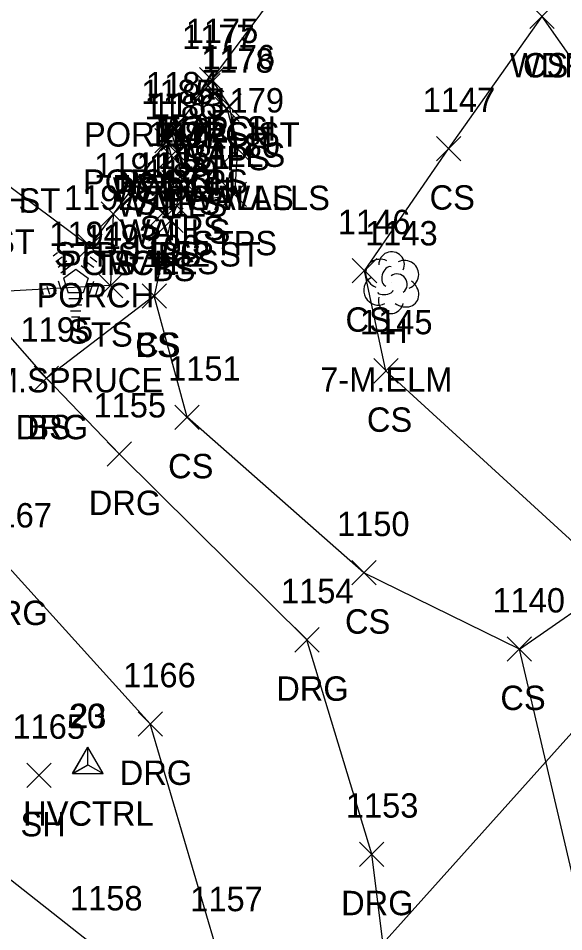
# Model space of a CAD drawing. Extents: x 1537342 to 1542195, y 163002 to 168596.
# Drawn here: x 1541986.2 to 1542030.9, y 163219.8 to 163294.7 of the extents above; entities that cross this region are included whole.
import ezdxf

# ---------------------------------------------------------------- set-up
doc = ezdxf.new("R2010")
doc.units = 0
for name, color, linetype in [('C_A', 7, 'Continuous'), ('C_I', 7, 'Continuous'), ('CPSM', 7, 'Continuous'), ('DCP', 7, 'Continuous'), ('L_A', 7, 'Continuous'), ('L_C', 7, 'Continuous'), ('L_I', 7, 'Continuous'), ('L_TIC', 7, 'Continuous'), ('LAWA', 7, 'Continuous'), ('LBF', 7, 'Continuous'), ('LELB', 7, 'Continuous'), ('LTC', 7, 'Continuous'), ('LTD', 7, 'Continuous'), ('LWS', 7, 'Continuous'), ('R_A', 7, 'Continuous'), ('R_I', 7, 'Continuous'), ('R_TIC', 7, 'Continuous'), ('RDG', 7, 'Continuous')]:
    doc.layers.add(name, color=color, linetype=linetype)

msp = doc.modelspace()

# ---------------------------------------------------------------- linework, layer by layer
at = {"layer": 'CPSM'}
for p, q in [((1541990.659, 163232.721), (1541991.909, 163234.886)), ((1541990.671, 163232.733), (1541991.921, 163234.898)), ((1541993.159, 163232.721), (1541991.909, 163234.886)), ((1541991.909, 163233.442), (1541991.909, 163234.886)), ((1541993.171, 163232.733), (1541991.921, 163234.898)), ((1541991.922, 163233.454), (1541991.921, 163234.898)), ((1541990.659, 163232.721), (1541991.909, 163233.442)), ((1541990.671, 163232.733), (1541991.922, 163233.454)), ((1541991.909, 163233.442), (1541991.909, 163233.442)), ((1541991.909, 163233.442), (1541993.159, 163232.721)), ((1541991.922, 163233.454), (1541991.922, 163233.454)), ((1541991.922, 163233.454), (1541993.171, 163232.733)), ((1541990.659, 163232.721), (1541993.159, 163232.721)), ((1541990.671, 163232.733), (1541993.171, 163232.733))]:
    msp.add_line(p, q, dxfattribs=at)
at = {"layer": 'DCP'}
msp.add_lwpolyline([(1541974.927, 163172.921), (1542058.961, 163266.56)], dxfattribs=at)
at = {"layer": 'L_TIC'}
for points in [[(1542028.159, 163293.803), (1542030.159, 163295.803)], [(1542030.159, 163293.803), (1542028.159, 163295.803)], [(1542028.159, 163293.803), (1542030.159, 163295.803)], [(1542030.159, 163293.803), (1542028.159, 163295.803)], [(1542001.066, 163288.621), (1542003.066, 163290.621)], [(1542003.066, 163288.621), (1542001.066, 163290.621)], [(1542001.066, 163288.621), (1542003.066, 163290.621)], [(1542003.066, 163288.621), (1542001.066, 163290.621)], [(1542000.763, 163288.132), (1542002.763, 163290.132)], [(1542002.763, 163288.132), (1542000.763, 163290.132)], [(1542000.763, 163288.132), (1542002.763, 163290.132)], [(1542002.763, 163288.132), (1542000.763, 163290.132)], [(1542002.326, 163286.194), (1542004.326, 163288.194)], [(1542004.326, 163286.194), (1542002.326, 163288.194)], [(1542002.496, 163286.468), (1542004.496, 163288.468)], [(1542004.496, 163286.468), (1542002.496, 163288.468)], [(1541997.811, 163284.259), (1541999.811, 163286.259)], [(1541999.811, 163284.259), (1541997.811, 163286.259)], [(1541997.811, 163284.259), (1541999.811, 163286.259)], [(1541999.811, 163284.259), (1541997.811, 163286.259)], [(1541997.418, 163283.621), (1541999.418, 163285.621)], [(1541999.418, 163283.621), (1541997.418, 163285.621)], [(1541997.418, 163283.621), (1541999.418, 163285.621)], [(1541999.418, 163283.621), (1541997.418, 163285.621)], [(1541997.75, 163282.381), (1541999.75, 163284.381)], [(1541999.75, 163282.381), (1541997.75, 163284.381)], [(1541998.276, 163282.559), (1542000.276, 163284.559)], [(1542000.276, 163282.559), (1541998.276, 163284.559)], [(1542003.185, 163282.928), (1542005.185, 163284.928)], [(1542005.185, 163282.928), (1542003.185, 163284.928)], [(1542003.185, 163282.928), (1542005.185, 163284.928)], [(1542005.185, 163282.928), (1542003.185, 163284.928)], [(1542020.498, 163282.961), (1542022.498, 163284.961)], [(1542022.498, 163282.961), (1542020.498, 163284.961)], [(1541997.993, 163280.174), (1541999.993, 163282.174)], [(1541999.993, 163280.174), (1541997.993, 163282.174)], [(1541998.645, 163280.46), (1542000.645, 163282.46)], [(1542000.645, 163280.46), (1541998.645, 163282.46)], [(1542002.929, 163279.223), (1542004.929, 163281.223)], [(1542004.929, 163279.223), (1542002.929, 163281.223)], [(1541998.201, 163278.299), (1542000.201, 163280.299)], [(1542000.201, 163278.299), (1541998.201, 163280.299)], [(1541998.201, 163278.299), (1542000.201, 163280.299)], [(1542000.201, 163278.299), (1541998.201, 163280.299)], [(1541993.003, 163277.598), (1541995.003, 163279.598)], [(1541995.003, 163277.598), (1541993.003, 163279.598)], [(1541993.003, 163277.598), (1541995.003, 163279.598)], [(1541995.003, 163277.598), (1541993.003, 163279.598)], [(1541997.044, 163277.667), (1541999.044, 163279.667)], [(1541999.044, 163277.667), (1541997.044, 163279.667)], [(1541997.733, 163277.097), (1541999.733, 163279.097)], [(1541999.733, 163277.097), (1541997.733, 163279.097)], [(1541991.084, 163274.946), (1541993.084, 163276.946)], [(1541993.084, 163274.946), (1541991.084, 163276.946)], [(1542013.6, 163272.951), (1542015.6, 163274.951)], [(1542015.6, 163272.951), (1542013.6, 163274.951)], [(1541992.771, 163271.734), (1541994.771, 163273.734)], [(1541994.771, 163271.734), (1541992.771, 163273.734)], [(1541996.358, 163270.883), (1541998.358, 163272.883)], [(1541998.358, 163270.883), (1541996.358, 163272.883)], [(1541996.358, 163270.883), (1541998.358, 163272.883)], [(1541998.358, 163270.883), (1541996.358, 163272.883)], [(1542015.358, 163264.745), (1542017.358, 163266.745)], [(1542017.358, 163264.745), (1542015.358, 163266.745)], [(1541987.515, 163264.136), (1541989.515, 163266.136)], [(1541989.515, 163264.136), (1541987.515, 163266.136)], [(1541999.054, 163260.935), (1542001.054, 163262.935)], [(1542001.054, 163260.935), (1541999.054, 163262.935)], [(1542013.56, 163248.195), (1542015.56, 163250.195)], [(1542015.56, 163248.195), (1542013.56, 163250.195)], [(1542026.304, 163241.931), (1542028.304, 163243.931)], [(1542028.304, 163241.931), (1542026.304, 163243.931)], [(1542026.304, 163241.931), (1542028.304, 163243.931)], [(1542028.304, 163241.931), (1542026.304, 163243.931)], [(1541986.902, 163231.576), (1541988.902, 163233.576)], [(1541988.902, 163231.576), (1541986.902, 163233.576)]]:
    msp.add_lwpolyline(points, dxfattribs=at)
at = {"layer": 'LAWA'}
msp.add_lwpolyline([(1542191.372, 163069.259), (1542155.135, 163097.456), (1542123.955, 163126.283), (1542083.783, 163159.158), (1542082.853, 163172.309), (1542083.05, 163192.115), (1542078.54, 163207.244), (1542059.971, 163213.118), (1542055.906, 163226.595), (1542055.198, 163251.611), (1542037.645, 163282.729), (1542029.159, 163294.803)], dxfattribs=at)
at = {"layer": 'LBF'}
for points in [[(1542014.111, 163305.822), (1542002.066, 163289.621), (1542001.763, 163289.132), (1541998.811, 163285.259), (1541998.418, 163284.621), (1541994.003, 163278.598), (1541992.084, 163275.946), (1541981.643, 163283.712), (1541977.366, 163287.102), (1541969.383, 163292.994), (1541972.352, 163296.503)], [(1542001.763, 163289.132), (1542003.326, 163287.194), (1542004.185, 163283.928), (1542003.929, 163280.223), (1541999.201, 163279.299), (1541999.645, 163281.46), (1541999.276, 163283.559), (1541998.811, 163285.259)]]:
    msp.add_lwpolyline(points, dxfattribs=at)
at = {"layer": 'LELB'}
for points in [[(1542002.438, 163218.438), (1541992.576, 163218.503), (1541981.665, 163227.078), (1541972.727, 163235.185), (1541952.245, 163252.94), (1541934.224, 163270.875), (1541926.758, 163276.805), (1541931.045, 163280.387), (1541930.665, 163296.396), (1541914.432, 163302.118), (1541899.504, 163302.033), (1541884.497, 163311.998), (1541872.596, 163319.595), (1541857.311, 163324.696)], [(1542027.304, 163242.931), (1542035.268, 163248.442), (1542016.358, 163265.745), (1542014.6, 163273.951), (1542021.498, 163283.961), (1542029.159, 163294.803)], [(1541999.201, 163279.299), (1541998.733, 163278.097), (1541997.358, 163271.883), (1541988.515, 163265.136)], [(1541994.003, 163278.598), (1541993.771, 163272.734), (1541982.386, 163272.123)], [(1542019.327, 163189.823), (1542021.997, 163197.119), (1542023.923, 163212.012), (1542033.032, 163218.579), (1542027.304, 163242.931), (1542014.56, 163249.195), (1542000.054, 163261.935), (1541997.358, 163271.883)]]:
    msp.add_lwpolyline(points, dxfattribs=at)
at = {"layer": 'LTC'}
for p, q in [((1541989.072, 163275.188), (1541989.426, 163275.445)), ((1541992.47, 163275.428), (1541992.889, 163275.123)), ((1541989.281, 163274.722), (1541989.81, 163275.106)), ((1541989.491, 163274.256), (1541990.195, 163274.768)), ((1541991.728, 163274.731), (1541992.407, 163274.238)), ((1541992.099, 163275.08), (1541992.648, 163274.68)), ((1541989.7, 163273.79), (1541990.579, 163274.428)), ((1541989.925, 163273.335), (1541990.937, 163274.07)), ((1541990.937, 163274.07), (1541991.934, 163273.345)), ((1541991.357, 163274.383), (1541992.166, 163273.794)), ((1541989.47, 163273.116), (1541989.801, 163272.097)), ((1541989.925, 163273.335), (1541990.312, 163272.142)), ((1541991.934, 163273.345), (1541991.543, 163272.142)), ((1541992.371, 163273.074), (1541992.033, 163272.035)), ((1541988.104, 163272.467), (1541988.256, 163271.999)), ((1541988.56, 163272.683), (1541988.771, 163272.032)), ((1541989.015, 163272.9), (1541989.286, 163272.065)), ((1541992.816, 163272.824), (1541992.528, 163271.939)), ((1541993.26, 163272.574), (1541993.023, 163271.844)), ((1541993.705, 163272.323), (1541993.518, 163271.749)), ((1541991.543, 163272.142), (1541990.312, 163272.142)), ((1541991.504, 163271.642), (1541990.36, 163271.642)), ((1541991.42, 163271.142), (1541990.432, 163271.142)), ((1541991.337, 163270.642), (1541990.505, 163270.642)), ((1541991.253, 163270.142), (1541990.578, 163270.142))]:
    msp.add_line(p, q, dxfattribs=at)
at = {"layer": 'LTD'}
msp.add_line((1542016.777, 163273.027), (1542016.777, 163273.027), dxfattribs=at)
msp.add_line((1542016.777, 163273.027), (1542016.777, 163273.027), dxfattribs=at)
msp.add_arc((1542016.824, 163274.461), 1.047, 335.52715, 180.95627, dxfattribs=at)
for centre, major_axis, ratio, start_param, end_param in [((1542015.985, 163273.693), (1.21, -0.512), 0.895232, 1.570796, 4.712389), ((1542017.819, 163273.61), (-1.141, -0.483), 0.949671, 1.570796, 4.712389), ((1542016.569, 163273.485), (-0.208, -0.792), 0.645439, 3.141593, 6.283185), ((1542017.277, 163272.86), (-0.5, 0.667), 0.989748, 3.141593, 6.283185), ((1542015.694, 163272.318), (0.584, -1.042), 0.959034, 3.141593, 6.283185), ((1542017.777, 163272.193), (-1.09, 0.792), 0.841452, 1.570796, 4.712389), ((1542016.319, 163272.277), (-0.625, -0.083), 0.423636, 0, 3.141593), ((1542016.778, 163271.527), (0.265, 1.061), 0.942809, 1.570796, 4.712389)]:
    msp.add_ellipse(centre, major_axis=major_axis, ratio=ratio, start_param=start_param, end_param=end_param, dxfattribs=at)
at = {"layer": 'LWS'}
for points in [[(1542002.066, 163289.621), (1542003.496, 163287.468), (1542004.185, 163283.928)], [(1541998.418, 163284.621), (1541998.75, 163283.381), (1541998.993, 163281.174), (1541998.044, 163278.667)]]:
    msp.add_lwpolyline(points, dxfattribs=at)
at = {"layer": 'R_TIC'}
for points in [[(1541987.515, 163264.136), (1541989.515, 163266.136)], [(1541989.515, 163264.136), (1541987.515, 163266.136)], [(1541993.503, 163257.921), (1541995.503, 163259.921)], [(1541995.503, 163257.921), (1541993.503, 163259.921)], [(1542008.877, 163242.692), (1542010.877, 163244.692)], [(1542010.877, 163242.692), (1542008.877, 163244.692)], [(1541996.038, 163235.795), (1541998.038, 163237.795)], [(1541998.038, 163235.795), (1541996.038, 163237.795)], [(1542014.196, 163225.11), (1542016.196, 163227.11)], [(1542016.196, 163225.11), (1542014.196, 163227.11)]]:
    msp.add_lwpolyline(points, dxfattribs=at)
at = {"layer": 'RDG'}
for points in [[(1542017.62, 163206.917), (1542015.196, 163226.11), (1542009.877, 163243.692), (1541994.503, 163258.921), (1541988.515, 163265.136), (1541982.386, 163272.123), (1541977.907, 163278.251), (1541973.34, 163281.582), (1541963.148, 163285.487), (1541948.659, 163292.511), (1541930.665, 163296.396), (1541918.384, 163296.027), (1541913.61, 163296.24), (1541903.895, 163289.032)], [(1542002.848, 163214.546), (1542002.438, 163218.438), (1541997.038, 163236.795), (1541985.193, 163249.902), (1541958.701, 163267.577), (1541939.931, 163277.382), (1541931.045, 163280.387), (1541922.489, 163280.521), (1541918.32, 163277.033)]]:
    msp.add_lwpolyline(points, dxfattribs=at)

# ---------------------------------------------------------------- texts
at = {"layer": 'C_A'}
for p in [(1541986.602, 163228.442), (1541986.615, 163228.454)]:
    msp.add_text('HVCTRL', height=2, dxfattribs=at).set_placement(p)
at = {"layer": 'C_I'}
for s, p in [('20', (1541990.358, 163236.442)), ('23', (1541990.457, 163236.454))]:
    msp.add_text(s, height=2, dxfattribs=at).set_placement(p)
at = {"layer": 'L_A'}
for s, p in [('WDR', (1542026.521, 163289.803)), ('CS', (1542027.6, 163289.803)), ('WALLS', (1541997.609, 163284.621)), ('PORCH', (1541997.688, 163284.621)), ('POR STPS ST', (1541991.598, 163284.132)), ('PORCH', (1541997.385, 163284.132)), ('WALLS', (1541999.04, 163282.468)), ('STPS', (1541999.846, 163282.194)), ('POR STPS', (1541991.52, 163280.259)), ('PORCH', (1541994.433, 163280.259)), ('WALLS', (1541993.961, 163279.621)), ('PORCH', (1541994.04, 163279.621)), ('POR STPW ST', (1541971.226, 163278.712)), ('PORCH', (1541977.265, 163278.712)), ('STPS WALLS', (1541994.973, 163278.928)), ('STPS', (1541995.796, 163278.559)), ('WALLS', (1541999.729, 163278.928)), ('CS', (1542019.939, 163278.961)), ('WALLS', (1541994.293, 163278.381)), ('STPS', (1541996.165, 163276.46)), ('WALLS', (1541994.537, 163276.174)), ('STPW SWC ST', (1541968.696, 163275.339)), ('STPS', (1542000.449, 163275.223)), ('STPS BS2 ST', (1541989.162, 163274.299)), ('BS', (1541997.642, 163274.299)), ('PORCH', (1541989.625, 163273.598)), ('TS', (1541992.413, 163273.598)), ('WALLS', (1541993.588, 163273.667)), ('BS', (1541997.174, 163273.097)), ('PORCH', (1541987.706, 163270.946)), ('CS', (1542013.041, 163268.951)), ('H', (1542016.21, 163268.027)), ('S', (1541990.262, 163267.979)), ('TS', (1541992.18, 163267.734)), ('CS', (1541995.799, 163266.883)), ('BS', (1541995.799, 163266.883)), ('CS', (1542014.799, 163260.745)), ('BS', (1541986.956, 163260.136)), ('CS', (1541998.495, 163256.935)), ('CS', (1542013.001, 163244.195)), ('CS', (1542025.745, 163237.931)), ('CS', (1542025.745, 163237.931)), ('SH', (1541986.39, 163227.576))]:
    msp.add_text(s, height=2, dxfattribs=at).set_placement(p)
at = {"layer": 'L_C'}
for s, p in [('M.SPRUCE', (1541983.963, 163263.979)), ('7-M.ELM', (1542010.966, 163264.027))]:
    msp.add_text(s, height=2, dxfattribs=at).set_placement(p)
at = {"layer": 'L_I'}
for s, p in [('1177', (1541999.637, 163292.132)), ('1177', (1541999.637, 163292.132)), ('1175', (1541999.94, 163292.621)), ('1175', (1541999.94, 163292.621)), ('1176', (1542001.315, 163290.468)), ('1178', (1542001.201, 163290.194)), ('1184', (1541996.685, 163288.259)), ('1184', (1541996.685, 163288.259)), ('1185', (1541996.292, 163287.621)), ('1185', (1541996.292, 163287.621)), ('1179', (1542002.052, 163286.928)), ('1179', (1542002.052, 163286.928)), ('1147', (1542019.373, 163286.961)), ('1186', (1541996.569, 163286.381)), ('1183', (1541997.151, 163286.559)), ('1187', (1541996.868, 163284.174)), ('1182', (1541997.52, 163284.46)), ('1180', (1542001.717, 163283.223)), ('1181', (1541997.643, 163282.299)), ('1181', (1541997.643, 163282.299)), ('1191', (1541992.445, 163281.598)), ('1191', (1541992.445, 163281.598)), ('1188', (1541995.918, 163281.667)), ('1189', (1541996.599, 163281.097)), ('1192', (1541989.958, 163278.946)), ('1146', (1542012.419, 163276.951)), ('1194', (1541988.751, 163275.979)), ('1193', (1541991.645, 163275.734)), ('1143', (1542014.652, 163276.027)), ('1190', (1541995.146, 163274.883)), ('1190', (1541995.146, 163274.883)), ('1195', (1541986.39, 163268.136)), ('1145', (1542014.232, 163268.745)), ('1151', (1541998.495, 163264.935)), ('1150', (1542012.348, 163252.195)), ('1140', (1542025.092, 163245.931)), ('1140', (1542025.092, 163245.931)), ('1165', (1541985.729, 163235.576)), ('1158', (1541990.45, 163221.503)), ('1157', (1542000.312, 163221.438))]:
    msp.add_text(s, height=2, dxfattribs=at).set_placement(p)
at = {"layer": 'LTC'}
msp.add_text('.', height=1.037, rotation=270, dxfattribs=at).set_placement((1541990.819, 163273.083))
at = {"layer": 'R_A'}
for s, p in [('STPW SWC ST', (1541968.696, 163275.339)), ('DRG', (1541986.003, 163260.136)), ('DRG', (1541991.991, 163253.921)), ('DRG', (1541982.681, 163244.902)), ('DRG', (1542007.365, 163238.692)), ('DRG', (1541994.526, 163231.795)), ('DRG', (1542012.685, 163221.11))]:
    msp.add_text(s, height=2, dxfattribs=at).set_placement(p)
at = {"layer": 'R_I'}
for s, p in [('1195', (1541986.39, 163268.136)), ('1155', (1541992.377, 163261.921)), ('1167', (1541983.02, 163252.902)), ('1154', (1542007.751, 163246.692)), ('1166', (1541994.81, 163239.795)), ('1153', (1542013.071, 163229.11)), ('1157', (1542000.312, 163221.438))]:
    msp.add_text(s, height=2, dxfattribs=at).set_placement(p)

doc.saveas('drawing.dxf')
